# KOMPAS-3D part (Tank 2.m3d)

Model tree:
1. Plane XY
2. Plane ZX
3. Plane ZY
4. X Axis
5. Y Axis
6. Z Axis
7. Origin
8. Sketch:4
9. Sketch:5
10. Extrude:2
     Толщина стенки 1 = 1; Толщина стенки 2 = 1; Расстояние 1 = 1000; Расстояние 2 = 800
11. Extrude:3
     Толщина стенки 1 = 1; Толщина стенки 2 = 1; Расстояние 1 = 1930.76; Расстояние 2 = 310.366
12. Fillet:1
     Радиус = 400
13. Mirror Body:2
14. Offset Plane:1  (labels: Емкость 2)
     Расстояние = 2000
15. Sketch:6
16. Extrude:4
     Толщина стенки 1 = 1; Толщина стенки 2 = 1; Расстояние 1 = 10; Расстояние 2 = 1549.52
17. Offset Plane:2
     Расстояние = 2100
18. Sketch:7
19. Extrude:5
     Толщина стенки 1 = 1; Толщина стенки 2 = 1; Расстояние 1 = 263; Расстояние 2 = 1
20. Linear Pattern:1  (labels: Экземпляр ( 2, 1 );)
21. Операция выдавливания:5
     N 1 = 2; Шаг 1 = 500; Угол раствора = 90; N 2 = 1; Шаг 2 = 10
22. Offset Plane:3
     Расстояние = 200
23. Sketch:10
24. Extrude:6  (labels: C:\Program Files\ASCON\KOMPAS-3D V10\Sys\graphic.lyt; T.002; Tank 2; Tank 2.m3d)
     Толщина стенки 1 = 1; Толщина стенки 2 = 1; Расстояние 1 = 263; Расстояние 2 = 1

Referenced files in C:\Documents and Settings\kashirsky\Мои документы\Camtasia Studio\Pipelines3D\Tanks\: Capacity_2.a3d, Tank 2.m3d, Tank 2.a3d, Tank 2.spw
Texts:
  Tank 2
  Steel ASTM A295
  Three Point Plane
  Plane at Angle
  Line and Point Plane
  Axis through Two Vertices
  Axis of Feature
  Axis of Conical Surface
  Axis through Edge
  Приклеить элемент выдавливания
  Приклеить элемент вращения
  Приклеить кинематический элемент
  Приклеить элемент по сечениям
  Trim by Surface
  Trim by Sketch
  Feature with No History
  Intersection Axis of Two Planes
  Two Line Plane
  Line and Face Plane
  Bend by line
  Hole in sheet body
  Cut in sheet body
  Point in CM
  Linear Dimension from Line to Point
  Surface Finish Symbol
  Geometric Tolerance Symbol
  Текст на чертеже
  Линия-выноска #1
  Линия-выноска #2
  Линия-выноска #3
  Отклонения формы и база
  Марка координационной оси
  Марка/позиционное обозначение с линией-выноской
  Марка/позиционное обозначение на линии
  Марка/позиционное обозначение без линии-выноски
  Емкость 2
  Экземпляр ( 2, 1 );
